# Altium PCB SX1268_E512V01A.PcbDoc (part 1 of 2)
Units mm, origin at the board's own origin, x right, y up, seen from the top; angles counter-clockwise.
Board outline 89 x 58 mm, 2 copper layers (Top Layer, Bottom Layer), stack 0.22 mm thick; 87 components, 53 nets, 246 pads, 1394 vias.
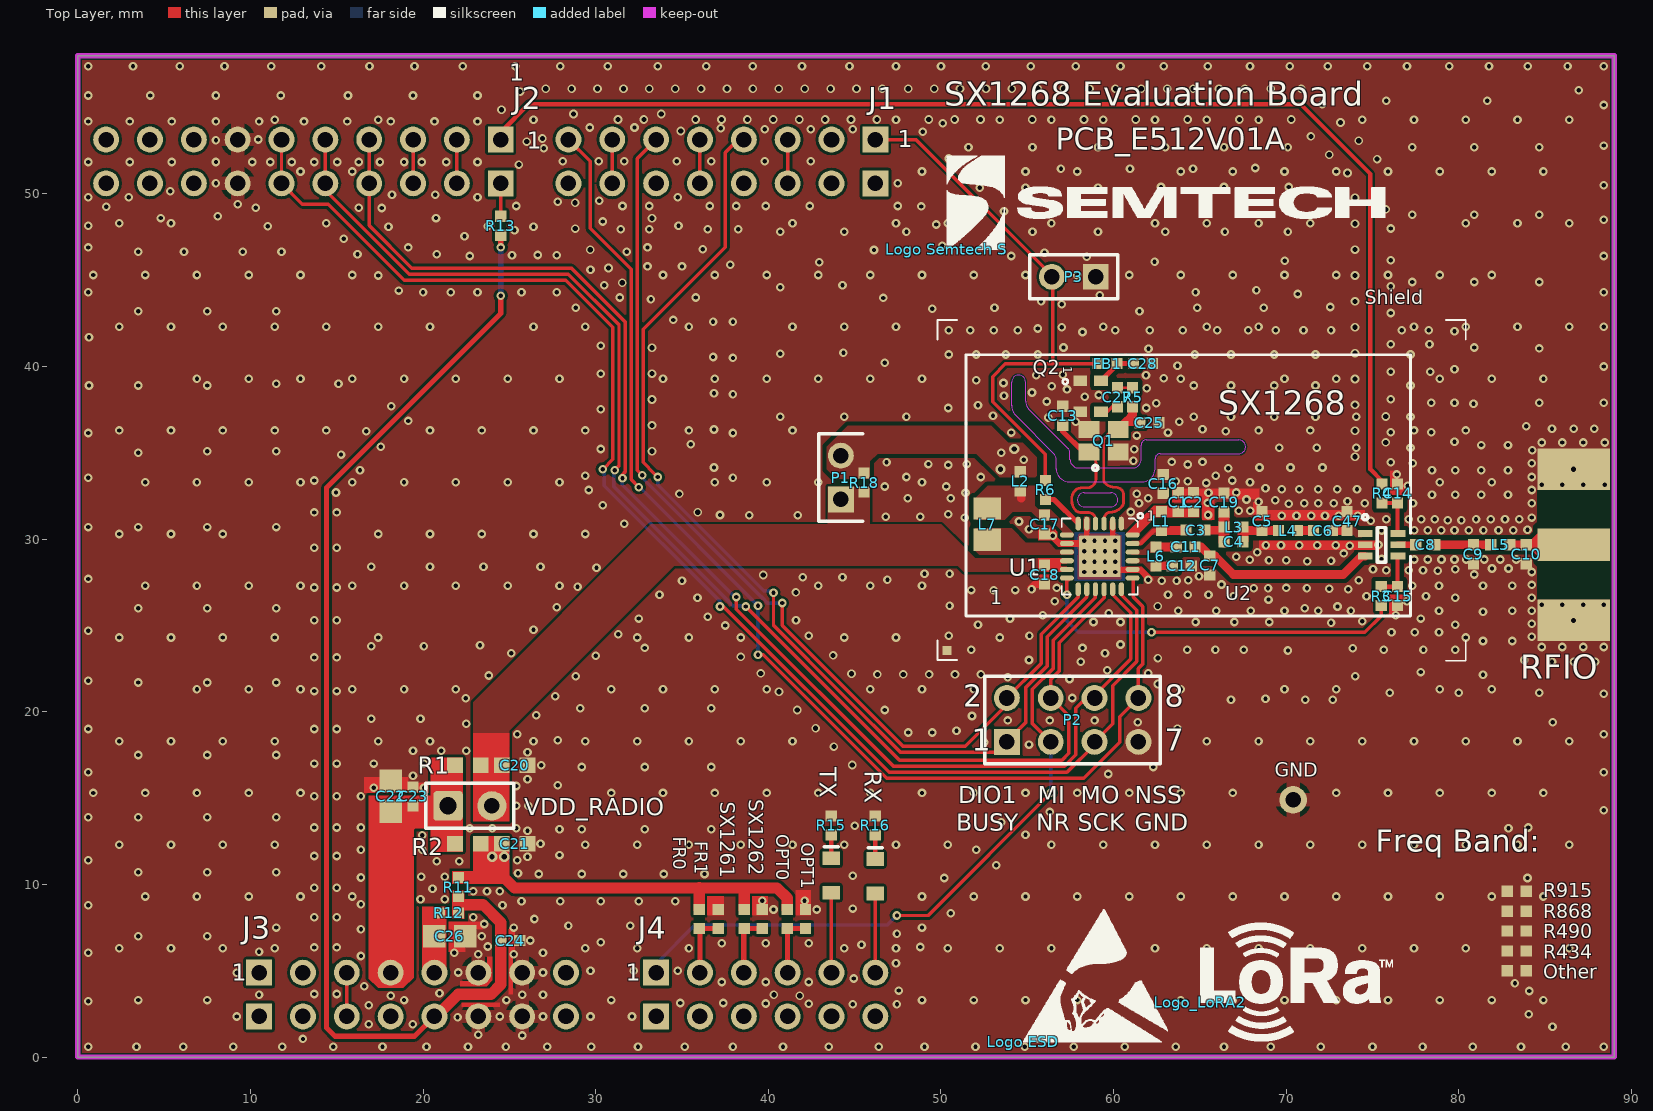
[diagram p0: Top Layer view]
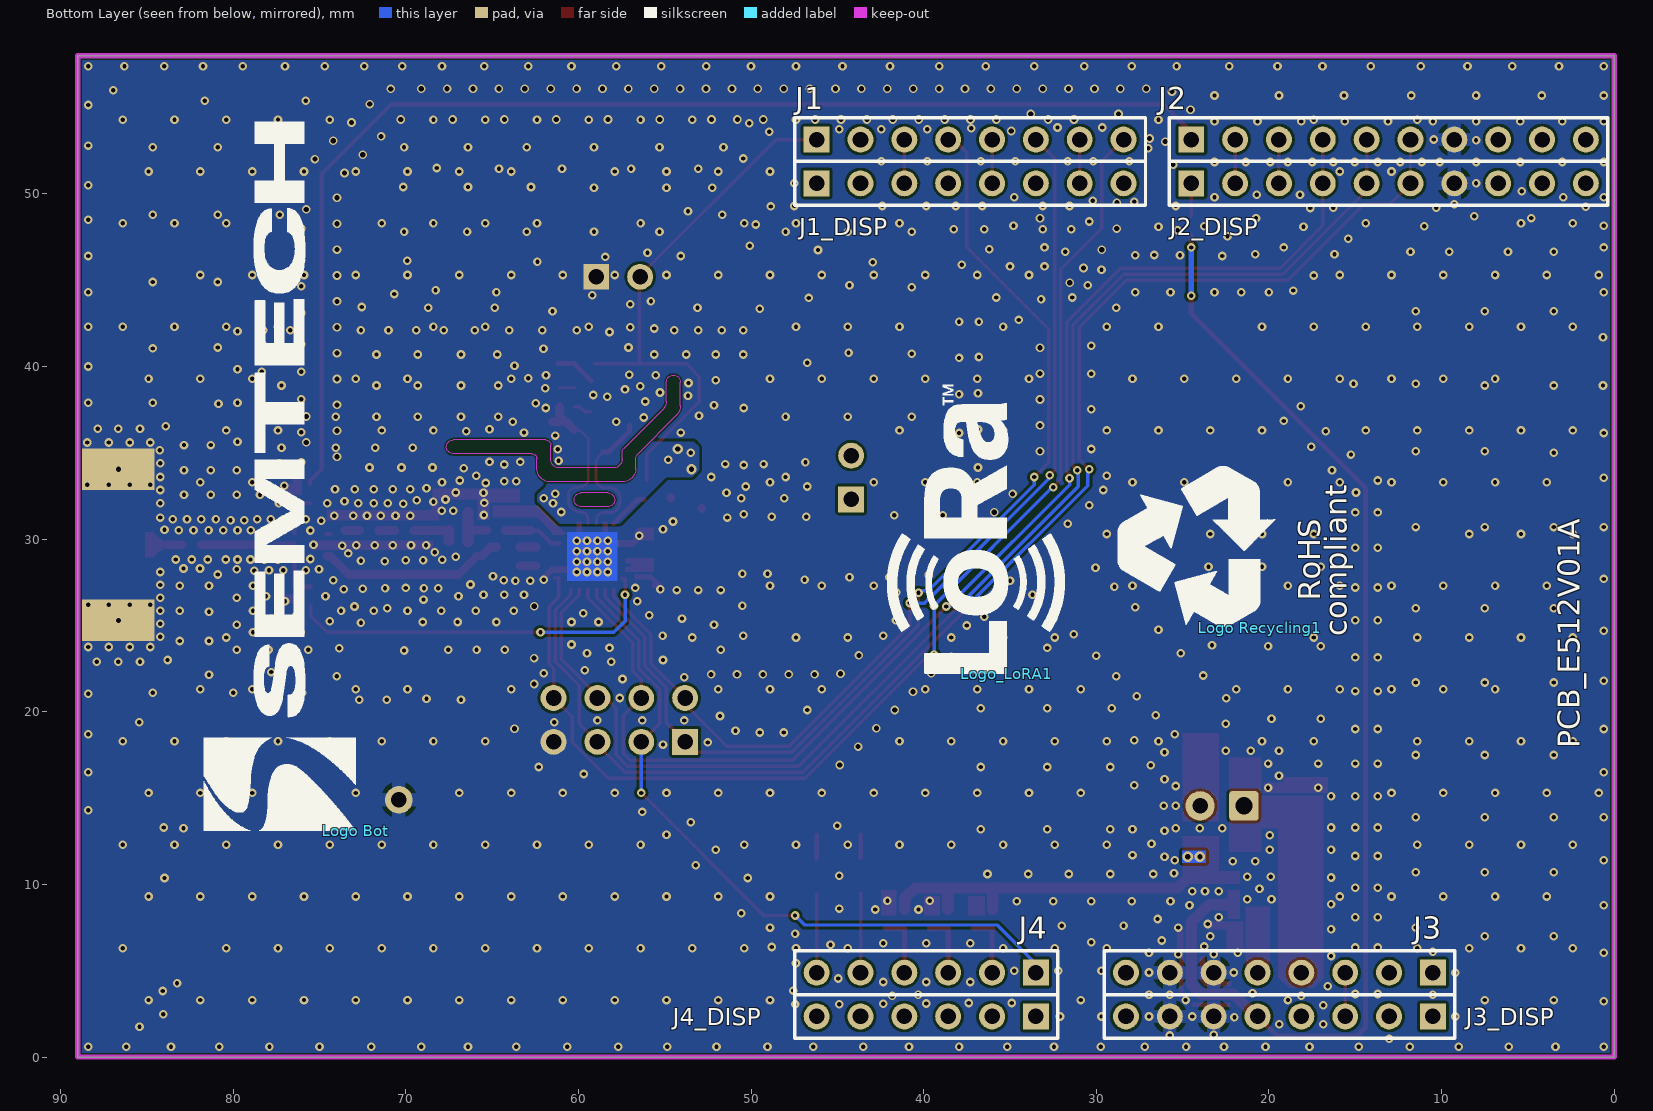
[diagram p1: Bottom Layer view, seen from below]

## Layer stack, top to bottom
Top Solder: solder mask 0.0102, Solder Resist, Dk 3.5
Top Layer: signal copper 0.035
Dielectric1: core 0.15, FR-4, Dk 4.4
Bottom Layer: signal copper 0.035
Bottom Solder: solder mask 0.0102, Solder Resist, Dk 3.5

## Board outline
0,0 0,58 89,58 89,0

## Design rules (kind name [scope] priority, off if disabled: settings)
Clearance Clearance_RF_GND [InNet('GND') And OnLayer('Top Layer') And (InPoly) vs InNet('NetL*') or InNet('NetC*') or InNet('NetU*')] p1: gap=0.254 ignorepadtopadclearanceinfootprint=FALSE
Clearance Clearance_GND_Keepout [(InNet('GND') OR InNet('XTA') OR InNet('XTB') OR InNet('NetC16_2')) vs OnLayer('Keep-Out Layer')] p2: gap=0.1 ignorepadtopadclearanceinfootprint=FALSE
Clearance Clearance_1 [All] p3: gap=0.15 ignorepadtopadclearanceinfootprint=FALSE
Clearance Clearance_GND [InNet('GND')] p4: gap=0.15 ignorepadtopadclearanceinfootprint=FALSE except(0: Arc-Hole Track-Hole SMDPad-Hole THPad-Hole Via-Hole Fill-Hole Poly-Hole Region-Hole Text-Hole)
Clearance [All] p5: gap=0.25 ignorepadtopadclearanceinfootprint=FALSE
ComponentClearance ComponentClearance_SMA_RFIO [InComponent('RFIO')] p1: gap=0.1 collisioncheckmode=3 verticalgap=0.1 showdistances=FALSE
ComponentClearance [All] p2: gap=0.2 collisioncheckmode=3 verticalgap=0.3 showdistances=FALSE
HoleSize [All] p1: absolutevalues=TRUE maxlimit=3.6 minlimit=0.25 maxpercent=80.000 minpercent=20.000
HoleToHoleClearance [All] p1: gap=0.2 allowstackedmicrovias=TRUE
MinimumSolderMaskSliver [All] p1: minsoldermaskwidth=0.04
PlaneClearance [All] p1: clearance=0.2
PlaneConnect [All] p1: planeconnectstyle=Direct reliefexpansion=0.508 reliefentries=4 reliefconductorwidth=0.254 reliefairgap=0.254
PolygonConnect "PolygonConnect SMD" [InNet('GND') vs HasFootprint('rlc_603_smd') or HasFootprint('rlc_402_smd') or hasFootprint('rlc_805_smd')  or hasFootprint('SOT353-5') or hasFootprint('VQFN24_4X4MM')   or hasFootprint('TCXO 2.0x1.6mm')  or HasFootprint('ND2016DA')  or HasFootprint('DFN6_3X3mm')   or HasFootprint('ODFN6_1.65X1.65mm')] p1 off: connectstyle=Relief reliefconductorwidth=0.4 reliefentries=4 polygonreliefangle="90 Angle" airgapwidth=0.254
PolygonConnect PolygonConnect_comp_diverse [InNet('GND') or  InNet('VDD_MBED') or  InNet('VDD_DISPLAY')  or  InNet('VDD_3V3')  or  InNet('VDD_RADIO')  or  InNet('VUSB') vs HasFootprint('LGM676 LED') or  HasFootprint('BRIDGE_254MM') or  HasFootprint('pin_0.9mm') or HasFootprint('SMA_STRAIGHT')  or  HasFootprint('HDR2X8')   or  HasFootprint('HDR2X6')  or  HasFootprint('HDR1X10') or  HasFootprint('vqfn20_3x3mm') or  HasFootprint('HDR1X9') or  HasFootprint('HDR1X8')  or  HasFootprint('HDR1X6') or  HasFootprint('HDR1X4')] p2: connectstyle=Relief reliefconductorwidth=0.8 reliefentries=4 polygonreliefangle="90 Angle" airgapwidth=0.254
PolygonConnect PolygonConnect_all [All] p3: connectstyle=Direct reliefconductorwidth=0.6 reliefentries=4 polygonreliefangle="90 Angle" airgapwidth=0.254
RoomDefinition SX1268_e407v02a_490MHz [InComponentClass('SX1268_e407v02a_490MHz')] p1: confinementstyle=ConfineOut formatcopy=TRUE lockcomponents=FALSE outline 13.5,81.35 13.45,81.4 13.45,124.35 67.45,124.35 67.3,124.2 67.3,81.35
RoutingVias [All] p1: holewidth=0.3 width=0.6 viastyle="Through Hole" minholewidth=0.25 minwidth=0.5 maxholewidth=0.4 maxwidth=0.8
SilkToSilkClearance [All] p1: silktosilkclearance=0.05
SilkToSolderMaskClearance SilkscreenOverComponentPads [IsPad] p1: minsilkscreentomaskgap=0.05 clearancetoexposedcopper=TRUE
SolderMaskExpansion [All] p1: expansion=0.05
Width "Width GND" [InNet('GND')] p1: maxlimit=3 minlimit=0.2 preferedwidth=0.4
Width Width_VCC [InNet('VDD') or  InNet('VDISPLAY') or  InNet('VDD_RADIO') or  InNet('VUSB') or  InNet('VDD_RADIO') or  InNet('VDD_MBED')] p2: maxlimit=2 minlimit=0.2 preferedwidth=0.8
Width "Width All" [All] p3: maxlimit=2 minlimit=0.15 preferedwidth=0.2
22 further rules are at their usual default settings.

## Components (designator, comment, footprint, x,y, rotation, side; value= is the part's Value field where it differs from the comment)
C1 "Cap" RLC_402_SMD 63.75,32.15 r270 top value=82pf
C2 "Cap" RLC_402_SMD 64.625,32.15 r270 top value=47nf
C3 "Cap" rlc_402_smd 64.75,30.525 r180 top value=0R
C4 "Cap" RLC_402_SMD 66.95,29.85 r180 top value=3pf
C5 "Cap" RLC_402_SMD 68.6,31.05 r270 top value=15pf
C6 "Cap" RLC_402_SMD 72.125,30.5 r180 top value=68pf
C7 "Cap" RLC_402_SMD 65.575,28.475 r90 top value=NC
C8 "Cap" RLC_402_SMD 78.05,29.675 r180 top value=68pf
C9 "Cap" RLC_402_SMD 80.85,29.125 r90 top value=NC
C10 "Cap" RLC_402_SMD 83.9,29.125 r90 top value=NC
C11 "Cap" RLC_402_SMD 64.175,29.55 r180 top value=NC
C12 "Cap" RLC_402_SMD 63.95,28.45 r180 top value=NC
C13 "Cap" rlc_402_smd 57.05,37.15 r270 top
C14 "Cap" RLC_402_SMD 76.45,32.65 r90 top value=1nF
C15 "Cap" RLC_402_SMD 76.45,26.7 r270 top value=1nF
C16 "Cap" RLC_402_SMD 62.875,33.2 r270 top value=10nF
C17 "Cap" RLC_402_SMD 56,30.85 r90 top value=470nF
C18 "Cap" RLC_402_SMD 56,27.95 r90 top value=100nF
C19 "Cap" rlc_402_smd 66.4,32.125 r90 top value=4.7pf
C20 "Cap" rlc_603_smd 25.3,16.9 r180 top value=1uF
C21 "Cap" rlc_603_smd 25.3,12.35 r180 top value=1uF
C22 "Cap" rlc_805_smd 18.12,15.1 r270 top value=10uF
C23 "Cap" RLC_402_SMD 19.42,15.1 r270 top value=100nF
C24 "Cap" RLC_402_SMD 25.05,6.75 r180 top value=1uF
C25 "Cap" rlc_402_smd 62.075,36.75 r180 top
C26 "Cap" rlc_805_smd 21.55,7 r180 top value=10uF
C27 "Cap" RLC_402_SMD 60.225,38.225 r90 top value=10pF
C28 "Cap" RLC_402_SMD 61.7,40.175 r180 top value=100nF
C47 "Cap" rlc_402_smd 73.525,31.05 r270 top value=8.2pf
FB1 "Ferrite beads" RLC_402_SMD 59.65,40.175 r0 top value=NC
FR0 "Resistor" RLC_402_SMD 36,8 r270 top value=1k
FR1 "Resistor" RLC_402_SMD 37.1,8 r270 top value=NC
GND "Test Pin" pin_0.9mm 70.4,14.9 r90 top
J1 "Header 8" HDR1X8 46.2,53.15 r180 bottom locked
J1_DISP "Header 8" HDR1X8 46.2,50.61 r180 bottom locked
J2 "Header 10" HDR1X10 24.5,53.15 r180 bottom locked
J2_DISP "Header 10" HDR1X10 24.5,50.61 r180 bottom locked
J3 "Header 8" HDR1X8 10.5,4.89 r0 bottom locked
J3_DISP "Header 8" HDR1X8 10.5,2.35 r0 bottom locked
J4 "Header 6" HDR1X6 33.5,4.89 r0 bottom locked
J4_DISP "Header 6" HDR1X6 33.5,2.35 r0 bottom locked
L1 "Inductor" RLC_402_SMD 62.775,31.05 r90 top value=56nh
L2 "Inductor" rlc_402_smd 54.6,33.35 r90 top value=48uH
L3 "Inductor" RLC_402_SMD 66.95,30.7 r0 top value=8.7nh
L4 "Inductor" RLC_402_SMD 70.1,30.5 r0 top value=18nh
L5 "Inductor" RLC_402_SMD 82.4,29.675 r0 top value=0R
L6 "Inductor" RLC_402_SMD 62.45,29 r90 top value=0R
L7 "Inductor" "rlc_805_smd enlarged" 52.675,30.875 r270 top value=15uH
"Logo Bot" "Logo symbol" logo_semtech_horiz_size4 72.9,13.1 r90 bottom
"Logo ESD" "Logo symbol" "Logo ESD" 54.764,0.9 r0 top
"Logo Recycling1" "Logo symbol" "Logo Recycling1" 20.527,24.87 r90 bottom
"Logo Semtech S" "Logo symbol" logo_semtech_horiz_size3 50.35,46.8 r0 top
Logo_LoRA1 "Logo symbol" "Logo LoRa Size4" 35.2,22.2 r90 bottom
Logo_LoRA2 "Logo symbol" "Logo LoRa Size3" 65.025,3.186 r0 top
OPT0 "Resistor" rlc_402_smd 41.1,8 r270 top value=1k
OPT1 "Resistor" rlc_402_smd 42.15,8 r270 top value=NC
Other "Resistor" RLC_402_SMD 83.35,5 r0 top value=NC
P1 "Header 2" HDR1X2 44.2,32.3 r90 top
P2 "Header 4X2" HDR2X4 53.82,18.26 r0 top
P3 "Header 2" HDR1X2 58.965,45.2 r180 top
Q1 "Xtal" nd2520da 59.425,35.7 r0 top value=32MHz
Q2 "TCXO" "TCXO 2.0x1.6mm" 58.675,38.275 r270 top value=32.0MHz
R1 "Resistor" rlc_603_smd 22.6,16.9 r180 top value=NC
R2 "Resistor" rlc_603_smd 22.6,12.35 r180 top value=0R
R3 "Resistor" RLC_402_SMD 75.5,26.7 r270 top value=100R
R4 "Resistor" RLC_402_SMD 75.55,32.65 r90 top value=100R
R5 "Resistor" rlc_402_smd 61.1,38.225 r270 top value=220R
R6 "Resistor" rlc_402_smd 56.05,32.85 r270 top value=0R
R11 "Resistor" RLC_402_SMD 22.05,9.85 r270 top value=NC
R12 "Resistor" RLC_402_SMD 21.5,8.35 r0 top value=0R
R13 "Resistor" RLC_402_SMD 24.5,48.15 r90 top value=10k
R15 "Resistor" RLC_402_SMD 43.65,13.421 r270 top value=330R
R16 "Resistor" RLC_402_SMD 46.2,13.421 r270 top value=330R
R18 "Resistor" RLC_402_SMD 45.55,33.275 r270 top value=0R
R434 "Resistor" RLC_402_SMD 83.35,6.15 r0 top value=NC
R490 "Resistor" rlc_402_smd 83.35,7.3 r180 top value=NC
R868 "Resistor" RLC_402_SMD 83.35,8.45 r0 top value=NC
R915 "Resistor" RLC_402_SMD 83.35,9.6 r180 top value=NC
RFIO "SMA" SMA_end_launch_1.0mm_9.52mm 86.65,29.675 r0 top locked
RX "LED" "LGM676 LED" 46.2,10.471 r90 top value=GREEN
Shield "Logo symbol" "BMIS-209-F - SHIELD" 50.35,23.55 r0 top locked
SX1261 "Resistor" RLC_402_SMD 38.6,8 r270 top value=NC
SX1262 "Resistor" RLC_402_SMD 39.65,8 r270 top value=1k
TX "LED" "LGM676 LED" 43.65,10.521 r90 top value=RED
U1 "SX1261/2" VQFN24_4X4MM 59.2,29 r270 top locked
U2 "PE4259 RF Switch" SC70-6 75.525,29.675 r0 top
VDD_RADIO "Jumper" BRIDGE_254MM 21.45,14.55 r0 top

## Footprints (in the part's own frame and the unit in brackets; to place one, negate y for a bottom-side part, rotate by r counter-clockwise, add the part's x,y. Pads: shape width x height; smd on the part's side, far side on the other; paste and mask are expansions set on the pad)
"BMIS-209-F - SHIELD" [mm] "BMIS-209-F EMI Gasket - modif SolderMask - Standard Surface Mount Shields -  Laird Technologies"
  rect 0.5x0.5 smd paste-1 mask+0.05: 1(0,0)
  Mechanical 15 keep-out lines w1: 0,0 29.5,0 29.5,18.6 0,18.6 0,0
  silkscreen extent -0.55,-0.6 30.05,19.15, body extent -0.3,-0.3 0.3,0.3, height 0.8
BRIDGE_254MM [mm] "Generic Bridge 2.54mm, 2 Leads 0.9mm;"
  rrect20% 1.7x1.7 hole 1 paste+0 mask+0.05: 1(0,0)
  round 1.7 hole 0.9 paste+0 mask+0.05: 2(2.54,0)
  silkscreen extent -1.3,-1.3 3.8,1.3, body extent -1.4,-1.4 3.9,1.4, height 1
HDR1X2 [mm] "Connector; Header; 2 Position"
  rect 1.5x1.5 hole 0.9: 1(0,0)
  round 1.5 hole 0.9: 2(2.54,0)
  silkscreen extent -1.27,-1.27 3.81,1.27
HDR1X6 [mm] "Connector; Header; 6 Position"
  rect 1.5x1.5 hole 0.9: 1(0,0)
  round 1.5 hole 0.9: 2(2.54,0) 3(5.08,0) 4(7.62,0) 5(10.16,0) 6(12.7,0)
  silkscreen extent -1.27,-1.27 13.97,1.27, body extent -0.8,-0.8 13.5,0.8
HDR1X8 [mm] "Connector; Header; 8 Position"
  rect 1.5x1.5 hole 0.9: 1(0,0)
  round 1.5 hole 0.9: 2(2.54,0) 3(5.08,0) 4(7.62,0) 5(10.16,0) 6(12.7,0) 7(15.24,0) 8(17.78,0)
  silkscreen extent -1.27,-1.27 19.05,1.27, body extent -0.8,-0.8 18.58,0.8
HDR1X10 [mm] "Connector; Header; 10 Position"
  rect 1.5x1.5 hole 0.9: 1(0,0)
  round 1.5 hole 0.9: 2(2.54,0) 3(5.08,0) 4(7.62,0) 5(10.16,0) 6(12.7,0) 7(15.24,0) 8(17.78,0) 9(20.32,0) 10(22.86,0)
  silkscreen extent -1.27,-1.27 24.13,1.27, body extent -0.8,-0.8 23.66,0.8
HDR2X4 [mm] "Connector; Header; 4x2 Position"
  rect 1.5x1.5 hole 0.9: 1(0,0)
  round 1.5 hole 0.9: 2(0,2.54) 3(2.54,0) 4(2.54,2.54) 5(5.08,0) 6(5.08,2.54) 7(7.62,0) 8(7.62,2.54)
  silkscreen extent -1.27,-1.27 8.89,3.81
"LGM676 LED" [mm] "Chip Diode; Body 2.1 x 1.4 mm (LxW typ)"
  rect 0.8x1 smd mask+0.05: 1(-1,0) 2(1,0)
  silkscreen extent 1.65,-0.4 1.65,0.4, body extent -1.2,-0.7 1.2,0.7, height 12
"Logo ESD" [mm] "Logo ESD"
  silkscreen extent 0,0 8.38,7.67
"Logo LoRa Size3" [mm] "Logo LoRa Size3 - Top Overlay"
  silkscreen extent 0,-2.26 11.16,4.59
"Logo LoRa Size4" [mm] "Logo LoRa Size4 - Top Overlay"
  silkscreen extent 0,-3.38 16.73,6.89
"Logo Recycling1" [mm] "Logo Recycling1"
  silkscreen extent 0.05,-0.88 9.36,8.2
logo_semtech_horiz_size3 [mm] "Logo semtech horizontal - size3 - L"
  silkscreen extent 0,0 25.4,5.41
logo_semtech_horiz_size4 [mm] "Logo semtech horizontal - size4 - XL"
  silkscreen extent 0,0 41.07,8.79
nd2520da [mm] "Crystal SMD 2.5x2.0mm"
  rect 1.2x1 smd mask+0.05: 1(-0.85,-0.65) 2(0.85,-0.65) 3(0.85,0.65) 4(-0.85,0.65)
  silkscreen extent -0.63,-1.72 -0.33,-1.42, body extent -1.25,-1 1.25,1, height 1
pin_0.9mm [mm] "Generic Pin 0.9mm; 1 Lead"
  round 1.6 hole 0.9 mask+0.05: 1(0,0)
RLC_402_SMD [mm] "Chip SMD component 402; Body 1.0 x 0.5 mm (LxW typ)"
  rect 0.65x0.65 smd mask+0.05: 1(-0.55,0) 2(0.55,0)
  body extent -0.87,-0.33 0.87,0.33, height 0.8
rlc_402_smd [mm] "Chip SMD component 402; Body 1.0 x 0.5 mm (LxW typ)"
  rect 0.65x0.65 smd mask+0.05: 1(-0.55,0) 2(0.55,0)
  body extent -0.87,-0.33 0.87,0.33, height 0.8
rlc_603_smd [mm] "Chip SMD component 603; Body 1.6 x 0.8mm (LxW typ)"
  rect 0.9x0.9 smd paste+0 mask+0.05: 1(-0.75,0) 2(0.75,0)
rlc_805_smd [mm] "Chip SMD component 805; Body 2.0 x 1.25 mm (LxW typ)"
  rect 1.3x1.3 smd mask+0.05: 1(-0.9,0) 2(0.9,0)
"rlc_805_smd enlarged" [mm] "Chip SMD component 805; Body 2.0 x 1.25 mm (LxW typ)"
  rect 1.3x1.6 smd mask+0.05: 1(-0.9,0) 2(0.9,0)
SC70-6 [mm] "SC70 6-Leads, Body 2.0x1.25mm, Pitch 0.65mm"
  rect 0.85x0.4 smd mask+0.05: 1(-0.95,0.65) 2(-0.95,0) 3(-0.95,-0.65) 4(0.95,-0.65) 5(0.95,0) 6(0.95,0.65)
  silkscreen extent -1.1,-1 0.25,1.75, body extent -0.63,-1 0.63,1, height 1.45
SMA_end_launch_1.0mm_9.52mm [mm] "SMA end launch for 1.0mm PCB thickness; 9.52mm"
  rect 4.2x1.905 smd mask+0.05: 1(0,0)
  rect 4.2x2.413 hole 0.3 mask+0.05: 2(0,-4.38) 2(0,4.38)
"TCXO 2.0x1.6mm" [mm] "SMD 2.0x1.6mm for TCXO or VCTCXO"
  rect 0.6x0.8 smd mask+0.05: 1(-0.9,-0.6) 2(0.9,-0.6) 3(0.9,0.6) 4(-0.9,0.6)
  silkscreen extent -1,-1.62 -0.7,-1.32, body extent -1,-0.8 1,0.8, height 1
VQFN24_4X4MM [mm] "24 Leads, Body 4.0x4.0mm, Pitch 0.50mm, VQFN24"
  oval 0.8x0.3 smd mask+0.05: 1(-1.9,1.25) 2(-1.9,0.75) 3(-1.9,0.25) 4(-1.9,-0.25) 5(-1.9,-0.75) 6(-1.9,-1.25) 13(1.9,-1.25) 14(1.9,-0.75) 15(1.9,-0.25) 16(1.9,0.25) 17(1.9,0.75) 18(1.9,1.25)
  oval 0.3x0.8 smd mask+0.05: 7(-1.25,-1.9) 8(-0.75,-1.9) 9(-0.25,-1.9) 10(0.25,-1.9) 11(0.75,-1.9) 12(1.25,-1.9) 19(1.25,1.9) 20(0.75,1.9) 21(0.25,1.9) 22(-0.25,1.9) 23(-0.75,1.9) 24(-1.25,1.9)
  rrect5% 2.4x2.4 smd paste-2.5 mask+0.05: 25(0,0)
  Mechanical 15 keep-out lines w0.1: 2.5,-2.5 2.5,2.5 -2.5,2.5 -2.5,-2.5 2.5,-2.5
  silkscreen extent -2.5,-2.2 2.2,2.5, body extent -2,-2 2,2, height 1

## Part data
C1 C2 C3 C4 C5 C6 C7 C8 C9 C10 C11 C12 C13 C14 C15 C16 C17 C18 C19 C20 C21 C22 C23 C24 C25 C26 C27 C28 C47: "Capacitor SMD"
FR0 FR1 OPT0 OPT1 Other R1 R2 R3 R4 R5 R6 R11 R12 R13 R15 R16 R18 R434 R490 R868 R915 SX1261 SX1262: "Resistor SMD - IEC symbol version"
GND: library part test_pin
J1 J1_DISP J3 J3_DISP: "Header, 8-Pin"
J2 J2_DISP: "Header, 10-Pin"
J4 J4_DISP: "Header, 6-Pin"
L1 L2 L3 L4 L5 L6 L7: "Inductor SMD"
"Logo Bot" "Logo ESD" "Logo Recycling1" "Logo Semtech S" Logo_LoRA1 Logo_LoRA2: library part Logo, "Schematic symbol for Logo"
P1 P3: "Header, 2-Pin"
P2: "Header, 4-Pin, Dual row"
Q1: library part "Xtal GND", "Crystal with GND pins; 4 pins"
RFIO: "SMA Straight Connector"
Shield: library part Shield, "Shield - EMI Gasket - Standard Surface Mount Shields"
U1: library part SX126x, "SX1261/2 - Ultra low power RF transceiver"
U2: "PE4259 Peregrine RF Switch"
VDD_RADIO: "Jumper Wire"

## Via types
v1: diameter 0.5, hole 0.25, Top Layer to Bottom Layer, tented both sides, 1261 vias
v2: diameter 0.5, hole 0.3, Top Layer to Bottom Layer, tented both sides, 113 vias
v3: diameter 0.5, hole 0.25, Top Layer to Bottom Layer, tented top, 16 vias
v4: diameter 0.6, hole 0.3, Top Layer to Bottom Layer, tented both sides, 4 vias

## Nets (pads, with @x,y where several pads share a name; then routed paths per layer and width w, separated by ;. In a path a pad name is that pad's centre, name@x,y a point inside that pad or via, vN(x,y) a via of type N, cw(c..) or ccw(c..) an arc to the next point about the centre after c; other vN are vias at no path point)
ANT_SW: J2.1 R4.2 | length 71.4
  Top Layer w0.25: J2.1@24.5,53.15 24.5,53.575 26.125,55.2 70.825,55.2 74.875,51.15 74.875,34.05 75.55,33.375 R4.2@75.55,33.2
BUSY: J1.4 P2.1 U1.14 | length 62.3
  Top Layer w0.2: v1(33.6,33.6) 33.4,33.8 32.75,34.45 32.75,42.15 37.5,46.9 37.5,52.4 38.25,53.15 J1.4@38.58,53.15 ; v1(40.3,26.9) 40.3,25.003 44.403,20.9 44.405,20.9 47.655,17.65 54.065,17.65 54.17,17.755 54.17,18.63 54.9,19.36 54.9,21.401 56.15,22.651 56.15,24.35 58.45,26.65 U1.14@58.45,27.1
  Bottom Layer w0.2: v1@33.6,33.675 v1(33.6,33.6) 33.6,33.143 39.743,27 40.2,27 v1(40.3,26.9)
DIO1: J1.6 P2.2 U1.13 | length 58
  Top Layer w0.2: v1(32.7,33.7) 32.4,34 32.4,52.05 J1.6@33.5,53.15 ; v1(40.8,26.3) 40.8,25 47.8,18 51.4,18 53.725,20.325 53.725,20.725 55.8,22.8 55.8,24.5 57.95,26.65 U1.13@57.95,27.1
  Bottom Layer w0.2: v1(32.7,33.7) 32.7,33.548 39.598,26.65 39.607,26.65 39.9,26.357 39.9,26.35 39.95,26.3 40.7,26.3 40.8,26.2 v1(40.8,26.3)
DIO2: R3.2 U1.12 | length 22.1
  Top Layer w0.2: v1(57.3,26.775) U1.12@57.3,27.75 ; U1.12@57.4,27.65 U1.12@57.5,27.75 ; v1(62.2,24.6) 74.55,24.6 75.5,25.55 R3.2@75.5,26.15
  Bottom Layer w0.2: v1(57.3,26.775) 57.3,25.25 57.95,24.6 v1(62.2,24.6)
DISP_RESET: J3.3 J3_DISP.3 | length 2.5
  Top Layer w0.2: J3_DISP.3@15.58,2.35 J3.3@15.58,4.87
  Top Layer w0.3: J3.3@15.58,4.87 J3.3@15.6,4.89
F_CS: J1.7 J1_DISP.7 | length 2.5
  Top Layer w0.2: J1_DISP.7@30.96,50.61 J1.7@30.96,53.15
